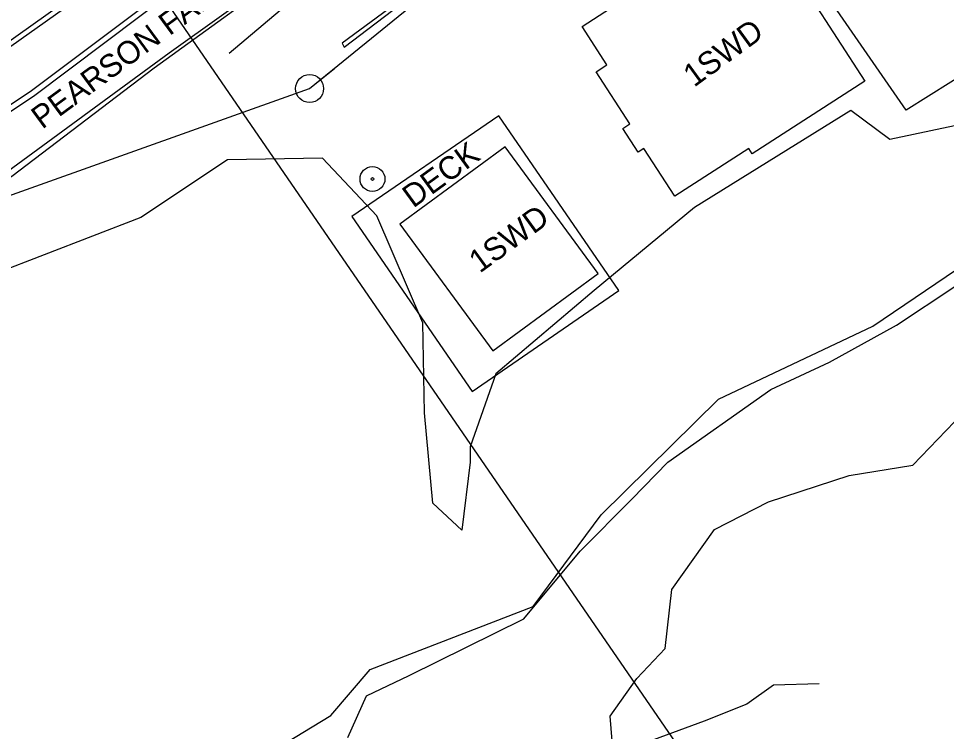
# Model space of a CAD drawing. Extents: x 1004911 to 1009660, y 551419 to 554278.
# Drawn here: x 1008711.1 to 1008873.5, y 551629 to 551753.8 of the extents above; entities that cross this region are included whole.
import ezdxf

# ---------------------------------------------------------------- set-up
doc = ezdxf.new("R2010")
doc.units = 0
for name, color, linetype in [('Default', 7, 'Continuous'), ('Exist Building Text', 7, 'Continuous'), ('Exist Hydro Jurisdictional Stream or Body of Water', 7, 'Continuous'), ('Exist Other Culture Area Outline Text', 7, 'Continuous'), ('Exist Property Line', 7, 'Continuous'), ('Exist Roads EOP Text', 7, 'Continuous'), ('Exist Roads EOT', 7, 'Continuous'), ('Prop DSN Text', 7, 'Continuous'), ('Sheet Cutting Line CELL', 7, 'Continuous'), ('Sheet Data Field CELL', 7, 'Continuous'), ('Sheet Plan Layout CELL', 7, 'Continuous'), ('Sheet Plot Border Inside CELL', 7, 'Continuous'), ('Sheet Plot Border Outside CELL', 7, 'Continuous'), ('Sheet Sticker Incomplete CELL', 7, 'Continuous')]:
    doc.layers.add(name, color=color, linetype=linetype)

msp = doc.modelspace()

# ---------------------------------------------------------------- linework, layer by layer
at = {"layer": 'Default'}
msp.add_lwpolyline([(1007889.69, 551637.93), (1008120.9, 551750.24), (1008475.69, 551639.38), (1008762.04, 551741.57), (1009077.06, 551997.55)], dxfattribs=at)
at = {"layer": 'Exist Hydro Jurisdictional Stream or Body of Water'}
for q in [(1008766.41, 551745.11), (1008762.04, 551741.57)]:
    msp.add_line((1008762.04, 551741.57), q, dxfattribs=at)
for points in [[(1008768.74, 551627.97), (1008771.98, 551635.29), (1008779.46, 551638.86), (1008799.54, 551648.73), (1008809.36, 551660.59), (1008818.4, 551669.73), (1008824.72, 551676.15), (1008842.75, 551688.91), (1008853.01, 551693.66), (1008864.69, 551700.14), (1008874.9, 551706.95)], [(1008851.17, 551637.35), (1008843.2, 551637.15), (1008838.53, 551633.84), (1008831.05, 551630.83), (1008818.89, 551626.35), (1008815, 551627.42), (1008814.62, 551631.7), (1008819.28, 551638.32), (1008824.24, 551643.57), (1008825.41, 551653.88), (1008832.89, 551664.39), (1008842.32, 551669.25), (1008856.42, 551673.82), (1008867.6, 551675.67), (1008874.89, 551683.26)]]:
    msp.add_lwpolyline(points, dxfattribs=at)
msp.add_circle((1008762.04, 551741.57), 2.45, dxfattribs=at)
at = {"layer": 'Exist Property Line'}
msp.add_line((1008719.33, 551782.42), (1008904.34, 551513.23), dxfattribs=at)
at = {"layer": 'Exist Roads EOT'}
for points in [[(1008907.36, 551903.22), (1008879.41, 551880.66), (1008855.98, 551861.62), (1008839.78, 551848.78), (1008823.61, 551836.36), (1008802.49, 551819.8), (1008768.8, 551792.98), (1008745.04, 551774.96), (1008718.97, 551755.48), (1008693.09, 551737.17), (1008691.4, 551736.19), (1008669.93, 551722.52), (1008659.64, 551716.93), (1008649.58, 551711.97), (1008627.47, 551702.88), (1008605.69, 551695.79), (1008594.51, 551692.62), (1008573.77, 551688.58), (1008546.23, 551684.51), (1008525.88, 551681.81), (1008499.74, 551678.82), (1008475.29, 551676.6), (1008445.08, 551674.72), (1008415.8, 551673.45)], [(1008912.31, 551896.8), (1008898.31, 551885.23), (1008876.2, 551867.75), (1008862.13, 551856.44), (1008833.3, 551833.81), (1008812.05, 551817), (1008790.81, 551800.18), (1008763.05, 551778.61), (1008738.1, 551759.79), (1008713.16, 551740.98), (1008683.27, 551721.08), (1008671.01, 551714.09), (1008656.85, 551707.01), (1008639.19, 551699.28), (1008619.53, 551692.16), (1008604.79, 551687.4), (1008589.87, 551683.74), (1008575.99, 551681.1), (1008555.57, 551677.32), (1008526.9, 551674.13), (1008498.23, 551670.93)], [(1008912.93, 551896.05), (1008898.92, 551884.47), (1008876.81, 551866.99), (1008862.74, 551855.68), (1008833.9, 551833.05), (1008812.65, 551816.23), (1008791.4, 551799.42), (1008763.64, 551777.84), (1008738.68, 551759.01), (1008713.72, 551740.19), (1008683.78, 551720.26), (1008671.47, 551713.24), (1008657.26, 551706.13), (1008639.55, 551698.38), (1008619.85, 551691.25), (1008605.06, 551686.46), (1008590.07, 551682.79), (1008576.17, 551680.15), (1008555.71, 551676.36), (1008527.02, 551673.16), (1008498.34, 551669.96)], [(1008566.64, 551669.73), (1008576.82, 551671.7), (1008592, 551674.49), (1008612.26, 551679.71), (1008643.79, 551691.47), (1008658.72, 551697.34), (1008667.45, 551701.6), (1008672.35, 551703.92), (1008686.7, 551712.54), (1008707.47, 551725.85), (1008737.45, 551747.81), (1008756.6, 551761.54), (1008783.28, 551782.1), (1008802.4, 551797.04), (1008821.67, 551812.04), (1008848.51, 551833.39), (1008865.56, 551846.23), (1008887.7, 551864.73), (1008906.57, 551880.14), (1008917.93, 551889.42)]]:
    msp.add_lwpolyline(points, dxfattribs=at)
for radius in [2.18, 0.24]:
    msp.add_circle((1008773.04, 551725.74), radius, dxfattribs=at)
at = {"layer": 'Prop DSN Text'}
for points in [[(1008809.71, 551752.45), (1008837.33, 551770.32), (1008841.76, 551763.45), (1008844.66, 551765.33), (1008859.18, 551742.89), (1008839.48, 551730.14), (1008838.88, 551731.08), (1008825.94, 551722.71), (1008820.53, 551731.08), (1008819.5, 551730.42), (1008816.81, 551734.58), (1008818.07, 551735.39), (1008812.18, 551744.5), (1008814.06, 551745.71)], [(1008777.81, 551717.84), (1008794.12, 551695.65), (1008812.55, 551709.2), (1008796.23, 551731.39)]]:
    msp.add_lwpolyline(points, close=True, dxfattribs=at)
at = {"layer": 'Sheet Cutting Line CELL'}
msp.add_lwpolyline([(1008747.96, 551747.75), (1008763.93, 551761.29), (1008780.03, 551773.11), (1008803.41, 551791.7), (1008824.31, 551807.5), (1008836.95, 551815.76), (1008852.44, 551825.58), (1008862.26, 551817.41)], dxfattribs=at)
at = {"layer": 'Sheet Data Field CELL'}
msp.add_lwpolyline([(1008769.45, 551719.15), (1008790.46, 551688.57), (1008816.14, 551706.22), (1008795.13, 551736.8)], close=True, dxfattribs=at)
at = {"layer": 'Sheet Plan Layout CELL'}
for points in [[(1008907.11, 551903.38), (1008877.31, 551879.59), (1008851.37, 551858.85), (1008822.68, 551836.33), (1008793.06, 551813.04), (1008765.92, 551791.92), (1008729.03, 551763.74), (1008703.1, 551745.29), (1008681.67, 551730.77), (1008667.7, 551721.91), (1008652.09, 551713.87), (1008633.01, 551705.65), (1008614.06, 551698.98), (1008597.93, 551694.24), (1008577.87, 551689.89), (1008557.3, 551686.65), (1008528.14, 551682.94), (1008498.99, 551679.22), (1008479.34, 551677.44), (1008447.75, 551675.38), (1008414.74, 551674.2)], [(1008424.58, 551654.63), (1008451.18, 551656.16), (1008477.9, 551658.42), (1008504.62, 551660.69), (1008545.78, 551665.53), (1008582.94, 551671.86), (1008595.16, 551674.7), (1008622.33, 551682.2), (1008649.94, 551692.27), (1008673.43, 551703.94), (1008684.82, 551710.61), (1008709.93, 551726.23), (1008734.87, 551745.19), (1008759.87, 551763.36), (1008797.37, 551791.77), (1008829.87, 551816.56), (1008849.37, 551833.07), (1008864.53, 551844.74), (1008903.81, 551876.93), (1008918.25, 551888.99)]]:
    msp.add_lwpolyline(points, dxfattribs=at)
at = {"layer": 'Sheet Plot Border Inside CELL'}
for points in [[(1008874.86, 551735.06), (1008863.57, 551732.68), (1008856.73, 551737.74), (1008829.39, 551720.78), (1008811.85, 551706.21), (1008794.61, 551691.64), (1008790.15, 551678.85), (1008790.15, 551676.17), (1008788.67, 551664.28), (1008783.62, 551669.03), (1008782.13, 551684.8), (1008781.83, 551700.56), (1008773.81, 551719.3), (1008764.3, 551729.41), (1008747.65, 551729.11), (1008732.49, 551719), (1008698.61, 551705.91)], [(1008427.25, 551560.48), (1008435.57, 551551.26), (1008444.19, 551545.9), (1008461.43, 551542.93), (1008492.34, 551543.52), (1008519.98, 551538.17), (1008528.3, 551550.96), (1008540.49, 551545.9), (1008555.95, 551553.04), (1008567.24, 551566.13), (1008622.23, 551570.29), (1008647.19, 551581), (1008676.32, 551575.35), (1008726.25, 551598.25), (1008721.5, 551613.71), (1008731.31, 551623.23), (1008746.76, 551620.26), (1008765.78, 551631.86), (1008772.62, 551639.89), (1008801.15, 551650.89), (1008813.04, 551666.95), (1008833.55, 551687.18), (1008860.6, 551699.97), (1008879.02, 551712.46)]]:
    msp.add_lwpolyline(points, dxfattribs=at)
at = {"layer": 'Sheet Plot Border Outside CELL'}
msp.add_lwpolyline([(1008767.71, 551749.49), (1008768.08, 551748.81), (1008786.32, 551762.77), (1008786.41, 551762.85), (1008798.23, 551772.14), (1008798.42, 551772.27), (1008807.2, 551778.81), (1008807.36, 551778.94), (1008814.22, 551783.95), (1008813.6, 551784.64), (1008807.05, 551779.64), (1008806.85, 551779.49), (1008798.09, 551772.71), (1008797.86, 551772.58), (1008786.11, 551763.15), (1008786.03, 551763.07)], close=True, dxfattribs=at)
at = {"layer": 'Sheet Sticker Incomplete CELL'}
msp.add_lwpolyline([(1008878.1, 551745.13), (1008866.41, 551737.78), (1008837, 551780.34), (1008855.17, 551789.35), (1008865.34, 551796.13), (1008869.95, 551799.64), (1008871.57, 551802.47), (1008871.84, 551806.03), (1008868.12, 551812.43), (1008860.23, 551823.66), (1008854.45, 551829.06), (1008849.37, 551833.07)], dxfattribs=at)

# ---------------------------------------------------------------- texts
at = {"layer": 'Exist Building Text'}
for p in [(1008829.3, 551741.71), (1008791.81, 551709.16)]:
    msp.add_text('1SWD', height=4, rotation=36.0731, dxfattribs=at).set_placement(p)
at = {"layer": 'Exist Other Culture Area Outline Text'}
msp.add_text('DECK', height=4, rotation=36.073, dxfattribs=at).set_placement((1008780.17, 551720.55))
at = {"layer": 'Exist Roads EOP Text'}
msp.add_text("PEARSON FALLS RD 20' BST", height=4, rotation=36.2955, dxfattribs=at).set_placement((1008715.26, 551734.35))

doc.saveas('drawing.dxf')
